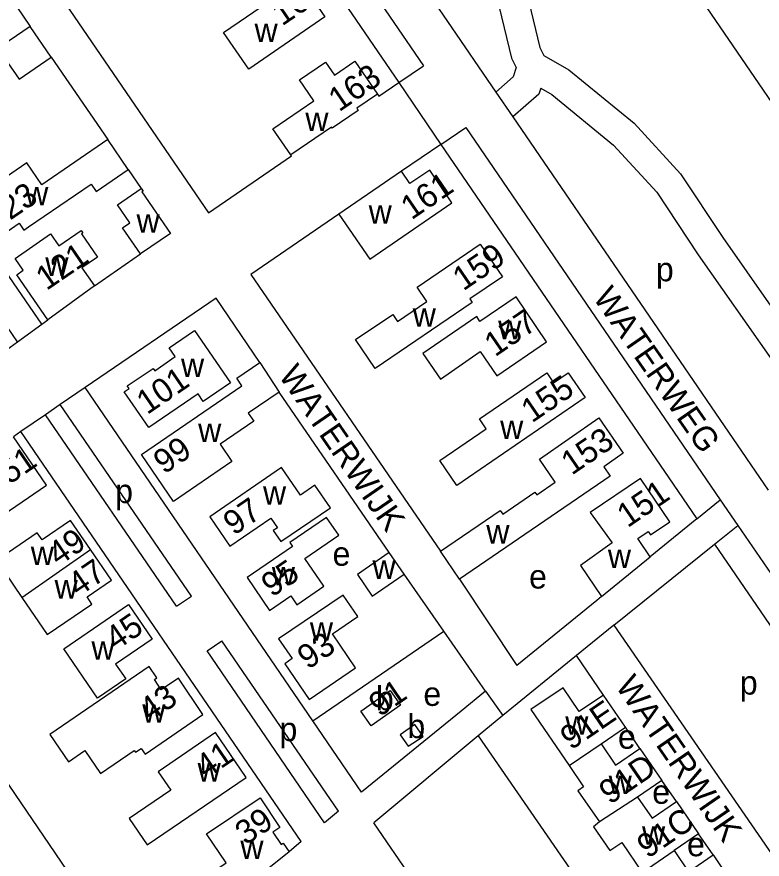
# Model space of a CAD drawing. Extents: x 154320 to 156262, y 382651 to 384180.
# Drawn here: x 155553.7 to 155678.1, y 383138.5 to 383279.2 of the extents above; entities that cross this region are included whole.
import ezdxf

# ---------------------------------------------------------------- set-up
doc = ezdxf.new("R2010")
doc.units = 0
for name, color, linetype in [('BLT_Basislijn', 7, 'Continuous'), ('BLT_Bebouwing', 7, 'Continuous'), ('BLT_Centroide', 7, 'Continuous'), ('BLT_Huisnummer', 7, 'Continuous'), ('BLT_Onderverdeling_panden', 7, 'Continuous'), ('BLT_Straatnaam', 7, 'Continuous'), ('BLT_Vlakafsluiter', 7, 'Continuous')]:
    doc.layers.add(name, color=color, linetype=linetype)

msp = doc.modelspace()

# ---------------------------------------------------------------- linework, layer by layer
at = {"layer": 'BLT_Basislijn'}
for p, q in [((155521.89, 383339.79), (155585.65, 383246.5)), ((155516.11, 383335.84), (155555.91, 383277.62)), ((155557.81, 383227.88), (155494.24, 383320.89)), ((155559.41, 383272.49), (155568.86, 383258.73)), ((155617.43, 383268.23), (155621.56, 383271.05)), ((155633.64, 383266.67), (155636.48, 383262.51)), ((155636.48, 383262.51), (155679.1, 383200.17)), ((155624.49, 383257.91), (155628.62, 383260.73)), ((155628.62, 383260.73), (155671.11, 383198.56)), ((155624.49, 383257.91), (155617.91, 383253.43)), ((155572.26, 383253.75), (155574.45, 383250.56)), ((155553.76, 383224.94), (155536.48, 383250.22)), ((155607.44, 383246.26), (155592.71, 383236.18)), ((155566.61, 383234.3), (155574.32, 383239.61)), ((155586.93, 383232.23), (155565.05, 383217.28)), ((155594.25, 383221.48), (155586.93, 383232.23)), ((155557.81, 383227.88), (155558.84, 383228.62)), ((155553.76, 383224.94), (155557.81, 383227.88)), ((155551.33, 383223.18), (155553.76, 383224.94)), ((155565.05, 383217.28), (155560.92, 383214.46)), ((155603.08, 383161.63), (155565.05, 383217.28)), ((155615.86, 383189.72), (155597.48, 383216.52)), ((155560.92, 383214.46), (155558.45, 383212.76)), ((155582.8, 383182.45), (155560.92, 383214.46)), ((155558.45, 383212.76), (155554.33, 383209.93)), ((155580.31, 383180.77), (155558.45, 383212.76)), ((155554.33, 383209.93), (155553.09, 383209.08)), ((155601.14, 383141.44), (155554.33, 383209.93)), ((155667.22, 383195.39), (155671.11, 383198.56)), ((155667.22, 383195.39), (155659.44, 383189.03)), ((155670.14, 383191.12), (155674.04, 383194.27)), ((155674.04, 383194.27), (155700.59, 383155.44)), ((155653.33, 383177.6), (155670.14, 383191.12)), ((155670.14, 383191.12), (155697.12, 383151.65)), ((155624.97, 383176.58), (155618.34, 383186.11)), ((155580.31, 383180.77), (155582.8, 383182.45)), ((155651.27, 383182.38), (155650.49, 383181.74)), ((155650.49, 383181.74), (155637.18, 383170.86)), ((155533.34, 383178.68), (155570.55, 383124.16)), ((155653.33, 383177.6), (155647.11, 383172.52)), ((155653.33, 383177.6), (155684.15, 383132.85)), ((155603.08, 383161.63), (155624.97, 383176.58)), ((155631.93, 383166.58), (155624.97, 383176.58)), ((155585.42, 383173.29), (155587.89, 383175)), ((155607.36, 383146.52), (155587.89, 383175)), ((155605.02, 383144.61), (155585.42, 383173.29)), ((155647.11, 383172.52), (155634.83, 383162.49)), ((155651.63, 383165.92), (155647.11, 383172.52)), ((155631.93, 383166.58), (155627.85, 383163.25)), ((155631.93, 383166.58), (155634.83, 383162.49)), ((155627.85, 383163.25), (155611.24, 383149.69)), ((155634.83, 383162.49), (155630.7, 383159.12)), ((155611.24, 383149.69), (155603.08, 383161.63)), ((155657.71, 383157.02), (155655.3, 383160.58)), ((155630.7, 383159.12), (155613.26, 383144.61)), ((155630.7, 383159.12), (155664.96, 383109.46)), ((155663.8, 383148.13), (155661.39, 383151.63)), ((155607.36, 383146.52), (155605.02, 383144.61)), ((155622.57, 383130.99), (155613.26, 383144.61)), ((155669.92, 383139.21), (155667.48, 383142.76)), ((155601.14, 383141.44), (155599.13, 383139.76))]:
    msp.add_line(p, q, dxfattribs=at)
for points in [[(155557.79, 383364.33), (155621.56, 383271.05)], [(155553.66, 383361.51), (155617.43, 383268.23)], [(155585.2, 383337.53), (155633.64, 383266.67)], [(155733.58, 383186.21), (155650, 383308.48)], [(155632.03, 383296.17), (155634.22, 383280.82), (155636.28, 383272.35), (155637.06, 383270.79)], [(155637.02, 383296.55), (155639.14, 383281.76), (155641.01, 383274.08), (155641.67, 383272.76), (155645.83, 383270.38), (155656.73, 383261.45), (155664.48, 383253), (155671.55, 383242.34)], [(155637.06, 383270.79), (155636.52, 383269.19), (155633.64, 383266.67)], [(155613.9, 383266.31), (155614.13, 383265.97), (155617.43, 383268.23)], [(155641.15, 383267.3), (155640.81, 383266.31), (155636.48, 383262.51)], [(155641.15, 383267.3), (155642.99, 383266.25), (155653.29, 383257.81), (155660.53, 383249.91), (155667.45, 383239.48)], [(155624.49, 383257.91), (155662.55, 383202.22), (155667.22, 383195.39)], [(155585.65, 383246.5), (155599.52, 383255.98), (155599.39, 383256.17)], [(155671.55, 383242.34), (155687.98, 383218.88), (155690.87, 383213)], [(155667.45, 383239.48), (155683.66, 383216.32), (155686.81, 383209.93), (155685.72, 383204.53), (155686.3, 383198.84), (155690.95, 383194.35), (155697.74, 383194.35)], [(155592.71, 383236.18), (155624.42, 383189.94)], [(155671.11, 383198.56), (155674.04, 383194.27)], [(155627.57, 383185.3), (155637.18, 383170.86)]]:
    msp.add_lwpolyline(points, dxfattribs=at)
at = {"layer": 'BLT_Bebouwing'}
for p, q in [((155617.91, 383253.43), (155607.44, 383246.26)), ((155566.61, 383234.3), (155558.84, 383228.62)), ((155594.25, 383221.48), (155597.48, 383216.52)), ((155618.34, 383186.11), (155615.86, 383189.72)), ((155627.57, 383185.3), (155624.42, 383189.94)), ((155651.27, 383182.38), (155659.44, 383189.03)), ((155611.1, 383163.25), (155615.99, 383166.67)), ((155615.99, 383166.67), (155617.7, 383164.23)), ((155655.3, 383160.58), (155651.63, 383165.92)), ((155617.7, 383164.23), (155612.81, 383160.8)), ((155612.81, 383160.8), (155611.1, 383163.25)), ((155651.22, 383157.79), (155655.3, 383160.58)), ((155657.71, 383157.02), (155661.39, 383151.63)), ((155661.39, 383151.63), (155657.3, 383148.88)), ((155663.8, 383148.13), (155667.48, 383142.76)), ((155667.48, 383142.76), (155663.41, 383139.96)), ((155599.13, 383139.76), (155585.98, 383129.24)), ((155669.92, 383139.21), (155673.57, 383133.84))]:
    msp.add_line(p, q, dxfattribs=at)
for points in [[(155588.19, 383276.62), (155600.89, 383285.34), (155605.09, 383279.22), (155592.39, 383270.5)], [(155631.04, 383241.23), (155634.75, 383235.78), (155629.3, 383232.1), (155629.68, 383231.53), (155613.52, 383220.5), (155610.23, 383225.31), (155616.42, 383229.5), (155617.22, 383228.33), (155622.12, 383231.67), (155620.52, 383234.05)], [(155637.02, 383232.46), (155631, 383228.35), (155630.45, 383229.15), (155621.47, 383223), (155624.38, 383218.72), (155624.38, 383218.72), (155631.05, 383223.3), (155633.83, 383219.25), (155642.11, 383224.92)], [(155571.59, 383216.57), (155572.41, 383217.14), (155572.11, 383217.58), (155576.44, 383220.5), (155576.71, 383220.11), (155580.11, 383222.46), (155579.09, 383223.95), (155583.31, 383226.84), (155589.34, 383218.09), (155584.77, 383214.99), (155583.92, 383216.23), (155575.68, 383210.6)], [(155642.15, 383219.75), (155643.25, 383218.07), (155645.72, 383219.76), (155648.59, 383215.62), (155627.11, 383200.94), (155624.29, 383205.1), (155632.03, 383210.4), (155630.9, 383212.05)], [(155597.84, 383203.94), (155585.88, 383195.7), (155589.23, 383190.81), (155596.06, 383195.49), (155597.17, 383193.87), (155596.49, 383193.41), (155597.77, 383191.56), (155606.04, 383197.22), (155603.43, 383200.99), (155601.02, 383199.33)], [(155605.38, 383195.59), (155599.27, 383191.4), (155599.69, 383190.77), (155592.11, 383185.58), (155595.87, 383180.08), (155599.39, 383182.5), (155600.39, 383181.01), (155604.91, 383184.1), (155601.73, 383188.74), (155607.41, 383192.63)], [(155608.13, 383182.62), (155597.38, 383175.32), (155599.62, 383172.01), (155598.39, 383171.14), (155602.49, 383165.2), (155610.23, 383170.5), (155606.37, 383176.17), (155610.58, 383179.03)], [(155571.84, 383168.63), (155567.13, 383165.41), (155561.5, 383173.66), (155572.3, 383181.04), (155576.26, 383175.24), (155570.16, 383171.09)], [(155575.78, 383170.69), (155559.18, 383159.34), (155562.28, 383154.78), (155565.03, 383156.65), (155567.63, 383152.83), (155573.27, 383156.68), (155573.48, 383156.37), (155574.4, 383157.02), (155575.08, 383156.07), (155584.74, 383162.68), (155580.65, 383168.76), (155577.78, 383166.81), (155576.64, 383168.5), (155577.06, 383168.78)], [(155620.12, 383160.99), (155617.67, 383159.28), (155619.02, 383157.39), (155621.49, 383159.02)], [(155586.83, 383159.65), (155577.24, 383153.11), (155579.35, 383150.02), (155572.43, 383145.28), (155575.44, 383140.89), (155591.94, 383152.14)]]:
    msp.add_lwpolyline(points, close=True, dxfattribs=at)
for points in [[(155555.91, 383277.62), (155535.85, 383263.95), (155535.27, 383263.55), (155538.79, 383258.4), (155539.37, 383258.8), (155550.28, 383266.23), (155548.41, 383268.96), (155552.18, 383271.54), (155554.05, 383268.82), (155559.41, 383272.49)], [(155559.41, 383272.49), (155555.91, 383277.62)], [(155599.39, 383256.17), (155596.41, 383260.52), (155603.23, 383265.18), (155600.84, 383268.7), (155605.19, 383271.65), (155606.68, 383269.49), (155610.12, 383271.83), (155613.9, 383266.31)], [(155613.9, 383266.31), (155610.43, 383263.97), (155610.68, 383263.6), (155606.32, 383260.63), (155606.21, 383260.8), (155599.39, 383256.17)], [(155568.86, 383258.73), (155557.86, 383251.18), (155555.35, 383254.85), (155551.05, 383251.9), (155545.74, 383248.23), (155550.01, 383242), (155554.04, 383244.77), (155554.82, 383243.61), (155555.61, 383244.15), (155566.05, 383251.29), (155566.91, 383250.06), (155572.26, 383253.75)], [(155572.26, 383253.75), (155568.86, 383258.73)], [(155607.44, 383246.26), (155612.61, 383238.75), (155626.31, 383248.16), (155622.61, 383253.59), (155619.31, 383251.36), (155617.91, 383253.43)], [(155574.32, 383239.61), (155571.3, 383243.96), (155572.54, 383244.82), (155570.47, 383247.8), (155574.45, 383250.56)], [(155574.45, 383250.56), (155574.74, 383250.14), (155574.52, 383249.98), (155579.33, 383243.06), (155574.32, 383239.61)], [(155558.84, 383228.62), (155553.67, 383236.14), (155554.73, 383236.89), (155553.37, 383238.87), (155559.31, 383242.99), (155560.68, 383241), (155564.39, 383243.55), (155564.69, 383243.12), (155564.47, 383242.97), (155567.12, 383239.1), (155564.54, 383237.32), (155566.61, 383234.3)], [(155597.48, 383216.52), (155592.31, 383213), (155593.22, 383211.68), (155587.59, 383207.83), (155589.59, 383204.94), (155579.83, 383198.29), (155574.5, 383206.14), (155591.24, 383217.58), (155590.38, 383218.84), (155594.25, 383221.48)], [(155624.42, 383189.94), (155634.39, 383196.76), (155634.82, 383196.13), (155640.17, 383199.8), (155640.47, 383199.37), (155643.57, 383201.5), (155640.94, 383205.34), (155650.84, 383212.26), (155654.9, 383206.35), (155651.66, 383204.07), (155652.76, 383202.5), (155627.57, 383185.3)], [(155543.82, 383202.76), (155549.35, 383194.7), (155558.6, 383201), (155553.09, 383209.08)], [(155659.44, 383189.03), (155657.36, 383192.07), (155659.08, 383193.25), (155659.46, 383192.69), (155662.68, 383194.89), (155657.79, 383202.11), (155649.41, 383196.43), (155653.05, 383191.35), (155647.79, 383187.59), (155651.27, 383182.38)], [(155565.97, 383190.26), (155562.65, 383195.11), (155557.9, 383191.86), (155557.08, 383193.05), (155550.27, 383188.4), (155554.5, 383182.23)], [(155554.5, 383182.23), (155558.74, 383176.03), (155566.2, 383181.13), (155565.38, 383182.33), (155569.49, 383185.14), (155565.97, 383190.26)], [(155615.86, 383189.72), (155610.54, 383186.06), (155613.01, 383182.45), (155618.34, 383186.11)], [(155651.63, 383165.92), (155647.57, 383163.16), (155644.87, 383167.15), (155639.51, 383163.51), (155645.89, 383154.14)], [(155651.22, 383157.79), (155653.65, 383154.24), (155657.71, 383157.02)], [(155645.89, 383154.14), (155648.3, 383150.61), (155647.32, 383149.94), (155650.94, 383144.76)], [(155585.98, 383129.24), (155582.75, 383133.96), (155588.63, 383137.9), (155585.36, 383142.77), (155594.27, 383148.74), (155597.6, 383143.82), (155596.39, 383143), (155597.78, 383140.94), (155598.14, 383141.18), (155599.13, 383139.76)], [(155657.3, 383148.88), (155659.73, 383145.34), (155663.8, 383148.13)], [(155650.94, 383144.76), (155649.96, 383143.94), (155652.71, 383139.96), (155654.69, 383141.3), (155658.09, 383136.29)], [(155663.41, 383139.96), (155665.82, 383136.42), (155669.92, 383139.21)]]:
    msp.add_lwpolyline(points, dxfattribs=at)
at = {"layer": 'BLT_Onderverdeling_panden'}
for p, q in [((155554.5, 383182.23), (155565.97, 383190.26)), ((155645.89, 383154.14), (155651.22, 383157.79)), ((155657.3, 383148.88), (155650.94, 383144.76)), ((155658.09, 383136.29), (155663.41, 383139.96))]:
    msp.add_line(p, q, dxfattribs=at)
at = {"layer": 'BLT_Vlakafsluiter'}
msp.add_line((155617.43, 383268.23), (155624.49, 383257.91), dxfattribs=at)

# ---------------------------------------------------------------- texts
at = {"layer": 'BLT_Centroide'}
for s, p in [('w', (155593.36, 383275.01)), ('w', (155601.84, 383260.15)), ('w', (155555.06, 383247.74)), ('w', (155612.41, 383244.68)), ('w', (155573.65, 383243.17)), ('w', (155558.42, 383235.96)), ('p', (155660.37, 383235.05)), ('w', (155619.77, 383227.45)), ('w', (155634.04, 383225.38)), ('w', (155581.08, 383219.05)), ('w', (155634.37, 383208.69)), ('w', (155583.94, 383208.18)), ('p', (155570.08, 383197.99)), ('w', (155594.77, 383197.75)), ('w', (155632.06, 383191.24)), ('w', (155555.99, 383187.65)), ('e', (155606.38, 383187.53)), ('w', (155652.36, 383187.15)), ('w', (155613.05, 383185.34)), ('w', (155596.24, 383184.26)), ('e', (155639.2, 383183.72)), ('w', (155559.97, 383182.05)), ('w', (155602.6, 383175)), ('w', (155566.12, 383171.83)), ('p', (155674.39, 383166.01)), ('b', (155613.62, 383163.4)), ('e', (155621.55, 383164.12)), ('w', (155574.61, 383161.3)), ('b', (155618.88, 383158.73)), ('w', (155645.24, 383159.32)), ('p', (155597.52, 383158.22)), ('e', (155654.04, 383156.96)), ('w', (155583.85, 383151.48)), ('w', (155652.49, 383149.39)), ('e', (155659.76, 383147.76)), ('w', (155658.06, 383140.91)), ('w', (155590.99, 383138.52)), ('e', (155665.57, 383139))]:
    msp.add_text(s, height=4, dxfattribs=at).set_placement(p)
at = {"layer": 'BLT_Huisnummer'}
for s, rotation, p in [('165', 34.3539, (155597.95, 383277.6)), ('163', 34.3539, (155607.47, 383263.26)), ('161', 34.3539, (155619.56, 383245.21)), ('123', 34.3538, (155550.09, 383243.49)), ('121', 34.3538, (155558.61, 383233.41)), ('159', 34.3539, (155628.21, 383233.34)), ('157', 34.3539, (155633.51, 383222.33)), ('101', 34.3538, (155575.42, 383212.68)), ('155', 34.3539, (155639.66, 383211.29)), ('153', 34.3539, (155646.32, 383202.56)), ('153', 34.3539, (155646.32, 383202.56)), ('99', 34.3538, (155578.25, 383202.72)), ('51', 34.3538, (155552.42, 383201.02)), ('151', 34.3539, (155655.64, 383193.78)), ('97', 34.3538, (155589.9, 383192.48)), ('49', 34.3538, (155560.61, 383187.37)), ('47', 34.3538, (155563.93, 383182.24)), ('95', 34.3538, (155596.26, 383182.16)), ('45', 34.3538, (155570.17, 383173.22)), ('93', 34.3538, (155602.28, 383170.08)), ('91', 34.3549, (155614.22, 383162.17)), ('43', 34.3538, (155575.88, 383161.33)), ('91E', 34.3538, (155646.19, 383156.63)), ('41', 34.3538, (155585.26, 383151.84)), ('91D', 34.3538, (155652.67, 383147.53)), ('39', 34.3538, (155591.88, 383140.73)), ('91C', 34.3538, (155659, 383138.51))]:
    msp.add_text(s, height=4, rotation=rotation, dxfattribs=at).set_placement(p)
at = {"layer": 'BLT_Straatnaam'}
for s, rotation, p in [('WATERWEG', 304.8259, (155649.75, 383232.34)), ('WATERWIJK', 304.5737, (155597.24, 383219.33)), ('WATERWIJK', 304.5737, (155653.5, 383167.44))]:
    msp.add_text(s, height=4, rotation=rotation, dxfattribs=at).set_placement(p)

doc.saveas('drawing.dxf')
